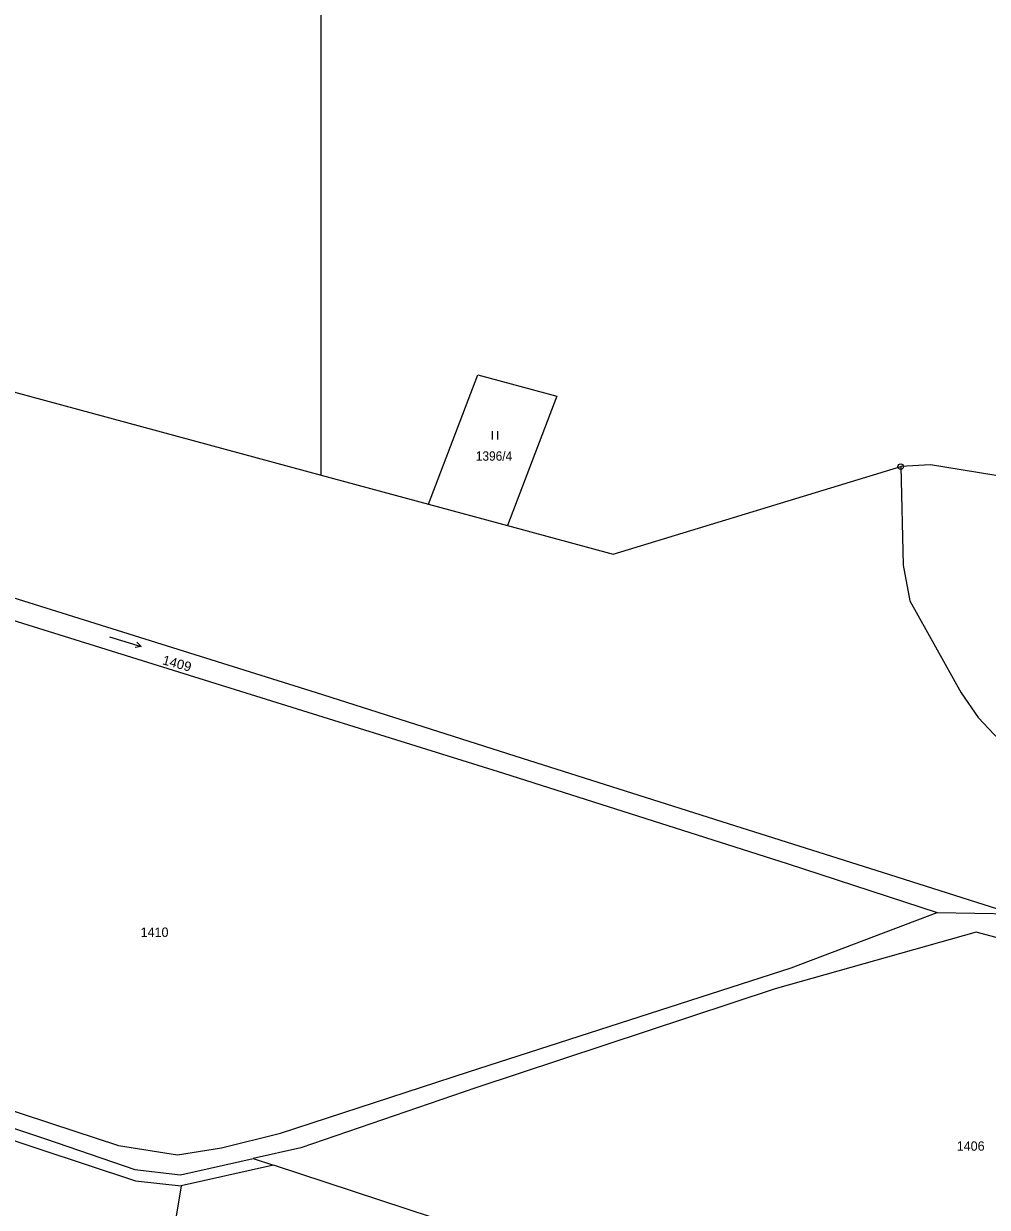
# Model space of a CAD drawing. Extents: x -872229 to -869198, y -1075981 to -1074329.
# Drawn here: x -870664.3 to -870489.5, y -1075366 to -1075151.2 of the extents above; entities that cross this region are included whole.
import ezdxf

# ---------------------------------------------------------------- set-up
doc = ezdxf.new("R2010")
doc.units = 0
doc.header["$LTSCALE"] = 0.68
for name, color, linetype, lineweight in [('1', 7, 'Continuous', 25), ('3', 7, 'Continuous', 25), ('4', 7, 'Continuous', 13), ('8', 7, 'Continuous', 25)]:
    doc.layers.add(name, color=color, linetype=linetype, lineweight=lineweight)
doc.layers.add('2', color=7, linetype='Continuous')

msp = doc.modelspace()

# ---------------------------------------------------------------- linework, layer by layer
at = {"layer": '1'}
for p, q in [((-870784.32, -1075186.07), (-870610.3, -1075233.15)), ((-870610.3, -1075233.15), (-870590.84, -1075238.42)), ((-870590.84, -1075238.42), (-870576.52, -1075242.29)), ((-870498.58, -1075312.54), (-870484.94, -1075312.75))]:
    msp.add_line(p, q, dxfattribs=at)
for points in [[(-870610.3, -1075233.15), (-870610.33, -1075122.57), (-870610.36, -1075011.6)], [(-870590.84, -1075238.42), (-870581.9, -1075214.94), (-870567.57, -1075218.82), (-870576.52, -1075242.29)], [(-870484.94, -1075312.75), (-870507.19, -1075305.67), (-870536.45, -1075296.46), (-870573.82, -1075284.57), (-870611.19, -1075272.67), (-870674.35, -1075252.89), (-870727.76, -1075235.26), (-870748.62, -1075229.44), (-870760.57, -1075227.08), (-870781.56, -1075223.68)], [(-870805.08, -1075225.21), (-870785.38, -1075227.74), (-870761.4, -1075230.4), (-870745.77, -1075233.67), (-870725.43, -1075240.95), (-870689.94, -1075252.08), (-870636.2, -1075268.85), (-870577.25, -1075287.24), (-870525.79, -1075303.65), (-870498.58, -1075312.54)], [(-870365.6, -1075255.58), (-870391.47, -1075252.55), (-870406.38, -1075247.4), (-870437.01, -1075244.1), (-870462.57, -1075237.4), (-870488.28, -1075233.18), (-870499.77, -1075231.3), (-870505.2, -1075231.6)], [(-870576.52, -1075242.29), (-870557.36, -1075247.48), (-870505.2, -1075231.6)], [(-870505.2, -1075231.6), (-870504.75, -1075249.5), (-870503.52, -1075255.95), (-870494.22, -1075272.65), (-870491.12, -1075277.11), (-870488.28, -1075280.14), (-870473.47, -1075293.92), (-870461.64, -1075297.33), (-870453.04, -1075301.3), (-870438.88, -1075307.81), (-870415.62, -1075316.62), (-870403.21, -1075323.85)], [(-870712.65, -1075330.89), (-870713.06, -1075332.91), (-870698.73, -1075337.79), (-870659.43, -1075350.77), (-870647.08, -1075354.82), (-870636.39, -1075356.51), (-870628.42, -1075355.25), (-870617.68, -1075352.56), (-870583.59, -1075341.47), (-870525.05, -1075322.56), (-870498.58, -1075312.54)], [(-870396.04, -1075325.73), (-870399.84, -1075327.3), (-870412.12, -1075330.68), (-870429.02, -1075333.26), (-870460.35, -1075324.44), (-870491.53, -1075316.1), (-870527.95, -1075326.37), (-870582.26, -1075344.32), (-870614.02, -1075355.21), (-870622.65, -1075357.15), (-870618.95, -1075358.37)], [(-870762.07, -1075321.97), (-870750.55, -1075325.97), (-870644.01, -1075361.21), (-870635.72, -1075362.14)], [(-870435.43, -1075418.82), (-870618.95, -1075358.37), (-870635.72, -1075362.14), (-870640.68, -1075391.97)]]:
    msp.add_lwpolyline(points, dxfattribs=at)
at = {"layer": '3'}
for p, q in [((-870579.261, -1075226.69), (-870579.261, -1075225.19)), ((-870578.26, -1075226.69), (-870578.26, -1075225.19)), ((-870642.987, -1075264.22), (-870644.068, -1075264.414))]:
    msp.add_line(p, q, dxfattribs=at)
msp.add_lwpolyline([(-870648.725, -1075262.466), (-870642.987, -1075264.22), (-870643.775, -1075263.455)], dxfattribs=at)
at = {"layer": '4'}
for p, q in [((-870692.51, -1075343.01), (-870660.32, -1075353.61)), ((-870660.32, -1075353.61), (-870644.14, -1075359.19))]:
    msp.add_line(p, q, dxfattribs=at)
msp.add_lwpolyline([(-870644.14, -1075359.19), (-870635.83, -1075360.11), (-870622.65, -1075357.15)], dxfattribs=at)
at = {"layer": '8'}
for radius in [0.5, 0.0303]:
    msp.add_circle((-870505.2, -1075231.5999), radius, dxfattribs=at)

# ---------------------------------------------------------------- texts
at = {"layer": '2', "width": 0.95}
msp.add_text('1396/4', height=1.7, dxfattribs=at).set_placement((-870582.27, -1075230.53))
at = {"layer": '2', "width": 1.05}
msp.add_text('1409', height=1.7, rotation=345, dxfattribs=at).set_placement((-870639.259, -1075267.451))
at = {"layer": '2'}
for s, p in [('1410', (-870643.08, -1075316.95)), ('1406', (-870495.03, -1075355.76))]:
    msp.add_text(s, height=1.7, dxfattribs=at).set_placement(p)

doc.saveas('drawing.dxf')
